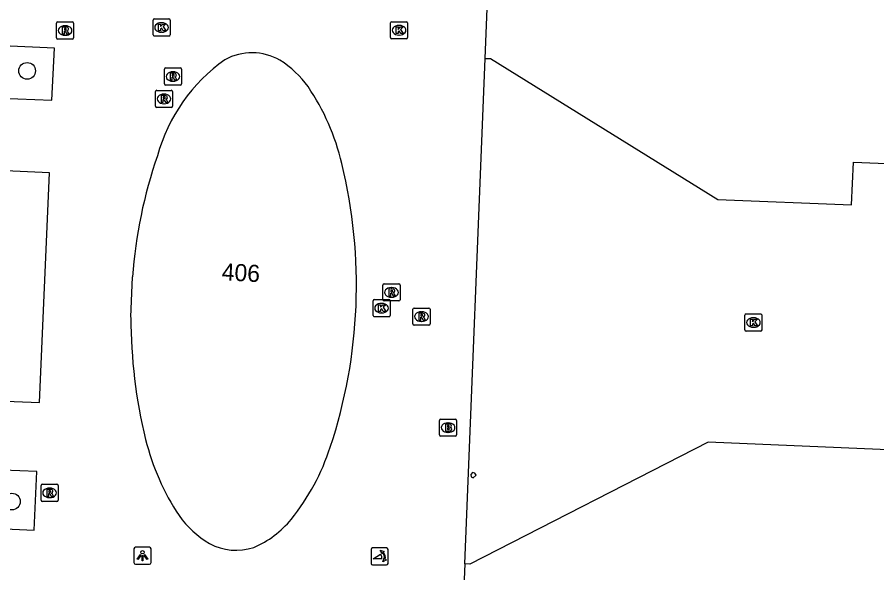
# Model space of a CAD drawing. Extents: x 160891 to 161384, y 386490 to 386907.
# Drawn here: x 161040.5 to 161090.7, y 386704.8 to 386737.3 of the extents above; entities that cross this region are included whole.
import ezdxf

# ---------------------------------------------------------------- set-up
doc = ezdxf.new("R2010")
doc.units = 0
for name, color, linetype in [('IMGEO_Boom', 7, 'Continuous'), ('IMGEO_Brandkraan', 7, 'Continuous'), ('IMGEO_Kolk', 7, 'Continuous'), ('IMGEO_Lichtpunt', 7, 'Continuous'), ('IMGEO_Pand', 7, 'Continuous'), ('IMGEO_Pand_nummerreeks', 7, 'Continuous'), ('IMGEO_Poller', 7, 'Continuous'), ('IMGEO_Rioolput', 7, 'Continuous'), ('IMGEO_Voetpad_open', 7, 'Continuous')]:
    doc.layers.add(name, color=color, linetype=linetype)

msp = doc.modelspace()

# ---------------------------------------------------------------- linework, layer by layer
at = {"layer": 'IMGEO_Boom'}
for centre in [(161041.064, 386734.18), (161040.172, 386709.011)]:
    msp.add_circle(centre, 0.489, dxfattribs=at)
at = {"layer": 'IMGEO_Brandkraan'}
for p, q in [((161065.15, 386712.904), (161065.15, 386713.756)), ((161065.225, 386713.83), (161066.077, 386713.83)), ((161066.151, 386713.756), (161066.151, 386712.904)), ((161065.638, 386713.61), (161065.663, 386713.61)), ((161066.077, 386712.83), (161065.225, 386712.83)), ((161065.661, 386713.05), (161065.636, 386713.05))]:
    msp.add_line(p, q, dxfattribs=at)
for points in [[(161065.15, 386712.904), (161065.15, 386713.756)], [(161065.225, 386713.83), (161066.077, 386713.83)], [(161066.151, 386713.756), (161066.151, 386712.904)], [(161065.498, 386713.53), (161065.498, 386713.13), (161065.711, 386713.13)], [(161065.729, 386713.53), (161065.498, 386713.53)], [(161065.677, 386713.449), (161065.623, 386713.449), (161065.623, 386713.373)], [(161065.623, 386713.373), (161065.676, 386713.373)], [(161065.685, 386713.297), (161065.623, 386713.297), (161065.623, 386713.216)], [(161065.623, 386713.216), (161065.685, 386713.216)], [(161066.077, 386712.83), (161065.225, 386712.83)]]:
    msp.add_lwpolyline(points, dxfattribs=at)
for centre, radius, start, end in [((161065.227, 386713.754), 0.0765, 91.552, 178.448), ((161065.227, 386713.754), 0.0765, 91.552, 178.448), ((161066.075, 386713.754), 0.0765, 1.552, 88.448), ((161066.075, 386713.754), 0.0765, 1.552, 88.448), ((161065.678, 386713.411), 0.0379, 267.8285, 90.9355), ((161065.686, 386713.256), 0.0404, 269.8759, 90.5077), ((161065.733, 386713.385), 0.145, 59.4692, 91.5367), ((161065.758, 386713.432), 0.0922, 285.5137, 58.1501), ((161065.763, 386713.24), 0.105, 301.3115, 78.989), ((161065.227, 386712.906), 0.0765, 181.552, 268.448), ((161065.227, 386712.906), 0.0765, 181.552, 268.448), ((161065.717, 386713.381), 0.251, 268.6676, 293.5347), ((161066.075, 386712.906), 0.0765, 271.552, 358.448), ((161066.075, 386712.906), 0.0765, 271.552, 358.448)]:
    msp.add_arc(centre, radius, start, end, dxfattribs=at)
for centre, major_axis, ratio, start_param, end_param in [((161065.637, 386713.33), (-0.387, 0.002), 0.722429, 4.712389, 7.853982), ((161065.662, 386713.33), (-0.39, 0.002), 0.717154, 1.570796, 4.712389)]:
    msp.add_ellipse(centre, major_axis=major_axis, ratio=ratio, start_param=start_param, end_param=end_param, dxfattribs=at)
at = {"layer": 'IMGEO_Kolk'}
for p, q in [((161048.417, 386736.292), (161048.417, 386737.144)), ((161048.492, 386737.218), (161049.344, 386737.218)), ((161048.905, 386736.998), (161048.93, 386736.998)), ((161049.418, 386737.144), (161049.418, 386736.292)), ((161062.29, 386736.131), (161062.29, 386736.983)), ((161062.365, 386737.057), (161063.217, 386737.057)), ((161062.778, 386736.837), (161062.803, 386736.837)), ((161063.291, 386736.983), (161063.291, 386736.131)), ((161048.928, 386736.438), (161048.903, 386736.438)), ((161049.344, 386736.218), (161048.492, 386736.218)), ((161063.217, 386736.057), (161062.365, 386736.057)), ((161062.801, 386736.277), (161062.776, 386736.277)), ((161061.269, 386719.888), (161061.269, 386720.74)), ((161061.344, 386720.814), (161062.196, 386720.814)), ((161062.27, 386720.74), (161062.27, 386719.888)), ((161061.757, 386720.594), (161061.782, 386720.594)), ((161062.196, 386719.814), (161061.344, 386719.814)), ((161061.78, 386720.034), (161061.755, 386720.034)), ((161082.987, 386719.047), (161082.987, 386719.899)), ((161083.062, 386719.973), (161083.914, 386719.973)), ((161083.475, 386719.753), (161083.5, 386719.753)), ((161083.988, 386719.899), (161083.988, 386719.047)), ((161083.914, 386718.973), (161083.062, 386718.973)), ((161083.498, 386719.193), (161083.473, 386719.193))]:
    msp.add_line(p, q, dxfattribs=at)
for points in [[(161048.417, 386736.292), (161048.417, 386737.144)], [(161048.492, 386737.218), (161049.344, 386737.218)], [(161048.738, 386736.918), (161048.861, 386736.918), (161048.861, 386736.767), (161048.991, 386736.918), (161049.155, 386736.918), (161049.009, 386736.767), (161049.162, 386736.518), (161049.01, 386736.518), (161048.925, 386736.682), (161048.861, 386736.615), (161048.861, 386736.518), (161048.738, 386736.518), (161048.738, 386736.918)], [(161049.418, 386737.144), (161049.418, 386736.292)], [(161062.29, 386736.131), (161062.29, 386736.983)], [(161062.365, 386737.057), (161063.217, 386737.057)], [(161063.291, 386736.983), (161063.291, 386736.131)], [(161062.611, 386736.757), (161062.734, 386736.757), (161062.734, 386736.606), (161062.864, 386736.757), (161063.028, 386736.757), (161062.882, 386736.606), (161063.035, 386736.357), (161062.883, 386736.357), (161062.798, 386736.521), (161062.734, 386736.454), (161062.734, 386736.357), (161062.611, 386736.357), (161062.611, 386736.757)], [(161049.344, 386736.218), (161048.492, 386736.218)], [(161063.217, 386736.057), (161062.365, 386736.057)], [(161061.269, 386719.888), (161061.269, 386720.74)], [(161061.344, 386720.814), (161062.196, 386720.814)], [(161062.27, 386720.74), (161062.27, 386719.888)], [(161061.59, 386720.514), (161061.713, 386720.514), (161061.713, 386720.363), (161061.843, 386720.514), (161062.007, 386720.514), (161061.861, 386720.363), (161062.014, 386720.114), (161061.862, 386720.114), (161061.777, 386720.278), (161061.713, 386720.211), (161061.713, 386720.114), (161061.59, 386720.114), (161061.59, 386720.514)], [(161062.196, 386719.814), (161061.344, 386719.814)], [(161082.987, 386719.047), (161082.987, 386719.899)], [(161083.062, 386719.973), (161083.914, 386719.973)], [(161083.988, 386719.899), (161083.988, 386719.047)], [(161083.308, 386719.673), (161083.431, 386719.673), (161083.431, 386719.522), (161083.561, 386719.673), (161083.725, 386719.673), (161083.579, 386719.522), (161083.732, 386719.273), (161083.58, 386719.273), (161083.495, 386719.437), (161083.431, 386719.37), (161083.431, 386719.273), (161083.308, 386719.273), (161083.308, 386719.673)], [(161083.914, 386718.973), (161083.062, 386718.973)]]:
    msp.add_lwpolyline(points, dxfattribs=at)
for centre, start, end in [((161048.494, 386737.142), 91.552, 178.448), ((161048.494, 386737.142), 91.552, 178.448), ((161049.342, 386737.142), 1.552, 88.448), ((161049.342, 386737.142), 1.552, 88.448), ((161062.367, 386736.981), 91.552, 178.448), ((161062.367, 386736.981), 91.552, 178.448), ((161063.215, 386736.981), 1.552, 88.448), ((161063.215, 386736.981), 1.552, 88.448), ((161048.494, 386736.294), 181.552, 268.448), ((161048.494, 386736.294), 181.552, 268.448), ((161049.342, 386736.294), 271.552, 358.448), ((161049.342, 386736.294), 271.552, 358.448), ((161062.367, 386736.133), 181.552, 268.448), ((161062.367, 386736.133), 181.552, 268.448), ((161063.215, 386736.133), 271.552, 358.448), ((161063.215, 386736.133), 271.552, 358.448), ((161061.346, 386720.738), 91.552, 178.448), ((161061.346, 386720.738), 91.552, 178.448), ((161062.194, 386720.738), 1.552, 88.448), ((161062.194, 386720.738), 1.552, 88.448), ((161061.346, 386719.89), 181.552, 268.448), ((161061.346, 386719.89), 181.552, 268.448), ((161062.194, 386719.89), 271.552, 358.448), ((161062.194, 386719.89), 271.552, 358.448), ((161083.064, 386719.897), 91.552, 178.448), ((161083.064, 386719.897), 91.552, 178.448), ((161083.912, 386719.897), 1.552, 88.448), ((161083.912, 386719.897), 1.552, 88.448), ((161083.064, 386719.049), 181.552, 268.448), ((161083.064, 386719.049), 181.552, 268.448), ((161083.912, 386719.049), 271.552, 358.448), ((161083.912, 386719.049), 271.552, 358.448)]:
    msp.add_arc(centre, 0.0765, start, end, dxfattribs=at)
for centre, major_axis, ratio, start_param, end_param in [((161048.904, 386736.718), (-0.387, 0.002), 0.722429, 4.712389, 7.853982), ((161048.929, 386736.718), (-0.39, 0.002), 0.717154, 1.570796, 4.712389), ((161062.777, 386736.557), (-0.387, 0.002), 0.722429, 4.712389, 7.853982), ((161062.802, 386736.557), (-0.39, 0.002), 0.717154, 1.570796, 4.712389), ((161061.756, 386720.314), (-0.387, 0.002), 0.722429, 4.712389, 7.853982), ((161061.781, 386720.314), (-0.39, 0.002), 0.717154, 1.570796, 4.712389), ((161083.474, 386719.473), (-0.387, 0.002), 0.722429, 4.712389, 7.853982), ((161083.499, 386719.473), (-0.39, 0.002), 0.717154, 1.570796, 4.712389)]:
    msp.add_ellipse(centre, major_axis=major_axis, ratio=ratio, start_param=start_param, end_param=end_param, dxfattribs=at)
at = {"layer": 'IMGEO_Lichtpunt'}
for p, q in [((161047.304, 386706.247), (161047.304, 386705.44)), ((161047.304, 386706.247), (161047.304, 386705.44)), ((161048.206, 386706.342), (161047.398, 386706.342)), ((161048.206, 386706.342), (161047.398, 386706.342)), ((161048.3, 386705.44), (161048.3, 386706.247)), ((161048.3, 386705.44), (161048.3, 386706.247)), ((161047.398, 386705.346), (161048.206, 386705.346)), ((161047.398, 386705.346), (161048.206, 386705.346))]:
    msp.add_line(p, q, dxfattribs=at)
for points in [[(161047.678, 386705.911), (161047.717, 386705.883), (161047.529, 386705.621), (161047.491, 386705.648), (161047.678, 386705.911)], [(161047.78, 386705.863), (161047.827, 386705.863), (161047.827, 386705.541), (161047.78, 386705.541), (161047.78, 386705.863)], [(161047.89, 386705.883), (161047.928, 386705.91), (161048.115, 386705.648), (161048.076, 386705.62), (161047.89, 386705.883)]]:
    msp.add_lwpolyline(points, dxfattribs=at)
msp.add_circle((161047.803, 386706.045), 0.0994, dxfattribs=at)
for centre, start, end in [((161047.398, 386706.247), 90, 180), ((161047.398, 386706.247), 90, 180), ((161048.206, 386706.247), 0, 90), ((161048.206, 386706.247), 0, 90), ((161047.398, 386705.44), 180, 270), ((161047.398, 386705.44), 180, 270), ((161048.206, 386705.44), 270, 0), ((161048.206, 386705.44), 270, 360)]:
    msp.add_arc(centre, 0.0946, start, end, dxfattribs=at)
at = {"layer": 'IMGEO_Pand'}
for points in [[(161067.82, 386734.914), (161068.422, 386750), (161068.579, 386753.93)], [(161067.82, 386734.914), (161068.128, 386734.901), (161081.411, 386726.666), (161089.223, 386726.344), (161089.335, 386728.855), (161138.981, 386726.813), (161138.885, 386724.445), (161161.551, 386723.521)], [(161047.127, 386719.777), (161047.22, 386722.145)], [(161127.462, 386710.495), (161080.851, 386712.475), (161066.929, 386705.356), (161066.624, 386705.366)], [(161067.221, 386710.676), (161067.078, 386710.699), (161066.975, 386710.596), (161066.998, 386710.453), (161067.127, 386710.387), (161067.287, 386710.547), (161067.221, 386710.676)], [(161066.624, 386705.366), (161065.189, 386671.013)]]:
    msp.add_lwpolyline(points, dxfattribs=at)
for centre, radius, start, end in [((161058.492, 386726.517), 10.182, 125.2343, 164.6202), ((161054.196, 386731.963), 3.275, 59.9847, 118.8039), ((161052.785, 386729.913), 5.759, 35.5324, 58.0373), ((161046.426, 386725.74), 13.363, 13.0848, 34.2475), ((161074.964, 386720.123), 27.818, 160.9175, 175.8307), ((161030.326, 386721.647), 29.974, 341.6232, 13.7384), ((161077.018, 386719.752), 29.891, 179.953, 193.7693), ((161061.976, 386716.123), 14.418, 193.9898, 213.4039), ((161045.912, 386716.393), 13.527, 321.4821, 341.9293), ((161054.654, 386711.527), 5.778, 215.3302, 239.4389), ((161051.945, 386711.745), 5.912, 293.5352, 320.3134), ((161053.283, 386709.533), 3.368, 242.2634, 287.6749)]:
    msp.add_arc(centre, radius, start, end, dxfattribs=at)
at = {"layer": 'IMGEO_Poller'}
for p, q in [((161061.151, 386706.205), (161061.151, 386705.398)), ((161061.151, 386706.205), (161061.151, 386705.398)), ((161062.053, 386706.3), (161061.245, 386706.3)), ((161062.053, 386706.3), (161061.245, 386706.3)), ((161062.147, 386705.398), (161062.147, 386706.205)), ((161062.147, 386705.398), (161062.147, 386706.205)), ((161061.245, 386705.303), (161062.053, 386705.303)), ((161061.245, 386705.303), (161062.053, 386705.303))]:
    msp.add_line(p, q, dxfattribs=at)
for points in [[(161061.786, 386705.656), (161061.273, 386705.656), (161061.703, 386705.931)], [(161061.83, 386706.029), (161061.818, 386705.956), (161061.693, 386706.161)], [(161061.693, 386706.161), (161061.924, 386706.095), (161061.853, 386706.063)], [(161061.846, 386705.484), (161061.912, 386705.715), (161061.942, 386705.647)], [(161061.978, 386705.62), (161062.05, 386705.609), (161061.846, 386705.484)]]:
    msp.add_lwpolyline(points, dxfattribs=at)
for centre, radius, start, end in [((161061.245, 386706.205), 0.0946, 90, 180), ((161061.245, 386706.205), 0.0946, 90, 180), ((161062.053, 386706.205), 0.0946, 0, 90), ((161062.053, 386706.205), 0.0946, 0, 90), ((161061.458, 386705.706), 0.332, 351.3247, 42.4854), ((161061.472, 386705.716), 0.476, 351.7527, 41.1691), ((161061.472, 386705.716), 0.516, 349.3569, 42.2912), ((161061.245, 386705.398), 0.0946, 180, 270), ((161061.245, 386705.398), 0.0946, 180, 270), ((161062.053, 386705.398), 0.0946, 270, 0), ((161062.053, 386705.398), 0.0946, 270, 0)]:
    msp.add_arc(centre, radius, start, end, dxfattribs=at)
at = {"layer": 'IMGEO_Rioolput'}
for p, q in [((161042.781, 386736.115), (161042.781, 386736.967)), ((161042.856, 386737.041), (161043.708, 386737.041)), ((161043.269, 386736.821), (161043.294, 386736.821)), ((161043.782, 386736.967), (161043.782, 386736.115)), ((161043.708, 386736.041), (161042.856, 386736.041)), ((161043.292, 386736.261), (161043.267, 386736.261)), ((161049.158, 386734.353), (161050.01, 386734.353)), ((161049.083, 386733.427), (161049.083, 386734.279)), ((161049.571, 386734.133), (161049.596, 386734.133)), ((161050.084, 386734.279), (161050.084, 386733.427)), ((161050.01, 386733.353), (161049.158, 386733.353)), ((161049.594, 386733.573), (161049.569, 386733.573)), ((161048.559, 386732.118), (161048.559, 386732.97)), ((161048.634, 386733.044), (161049.486, 386733.044)), ((161049.047, 386732.824), (161049.072, 386732.824)), ((161049.56, 386732.97), (161049.56, 386732.118)), ((161049.486, 386732.044), (161048.634, 386732.044)), ((161049.07, 386732.264), (161049.045, 386732.264)), ((161061.921, 386721.733), (161062.773, 386721.733)), ((161061.846, 386720.807), (161061.846, 386721.659)), ((161062.334, 386721.513), (161062.359, 386721.513)), ((161062.847, 386721.659), (161062.847, 386720.807)), ((161062.773, 386720.733), (161061.921, 386720.733)), ((161062.357, 386720.953), (161062.332, 386720.953)), ((161063.598, 386719.394), (161063.598, 386720.246)), ((161063.673, 386720.32), (161064.525, 386720.32)), ((161064.599, 386720.246), (161064.599, 386719.394)), ((161064.086, 386720.1), (161064.111, 386720.1)), ((161064.525, 386719.32), (161063.673, 386719.32)), ((161064.109, 386719.54), (161064.084, 386719.54)), ((161041.877, 386709.093), (161041.877, 386709.945)), ((161041.952, 386710.019), (161042.804, 386710.019)), ((161042.365, 386709.799), (161042.39, 386709.799)), ((161042.878, 386709.945), (161042.878, 386709.093)), ((161042.388, 386709.239), (161042.363, 386709.239)), ((161042.804, 386709.019), (161041.952, 386709.019))]:
    msp.add_line(p, q, dxfattribs=at)
for points in [[(161042.781, 386736.115), (161042.781, 386736.967)], [(161042.856, 386737.041), (161043.708, 386737.041)], [(161043.782, 386736.967), (161043.782, 386736.115)], [(161043.37, 386736.739), (161043.118, 386736.741), (161043.118, 386736.341)], [(161043.118, 386736.341), (161043.242, 386736.341), (161043.242, 386736.503), (161043.253, 386736.503)], [(161043.296, 386736.66), (161043.242, 386736.66), (161043.242, 386736.579)], [(161043.242, 386736.579), (161043.294, 386736.579)], [(161043.3, 386736.474), (161043.371, 386736.341), (161043.511, 386736.341), (161043.446, 386736.467)], [(161043.708, 386736.041), (161042.856, 386736.041)], [(161049.158, 386734.353), (161050.01, 386734.353)], [(161049.083, 386733.427), (161049.083, 386734.279)], [(161049.672, 386734.051), (161049.42, 386734.053), (161049.42, 386733.653)], [(161049.42, 386733.653), (161049.544, 386733.653), (161049.544, 386733.815), (161049.555, 386733.815)], [(161049.598, 386733.972), (161049.544, 386733.972), (161049.544, 386733.891)], [(161049.544, 386733.891), (161049.596, 386733.891)], [(161049.602, 386733.786), (161049.673, 386733.653), (161049.813, 386733.653), (161049.748, 386733.779)], [(161050.084, 386734.279), (161050.084, 386733.427)], [(161050.01, 386733.353), (161049.158, 386733.353)], [(161048.559, 386732.118), (161048.559, 386732.97)], [(161048.634, 386733.044), (161049.486, 386733.044)], [(161049.56, 386732.97), (161049.56, 386732.118)], [(161049.148, 386732.742), (161048.896, 386732.744), (161048.896, 386732.344)], [(161048.896, 386732.344), (161049.02, 386732.344), (161049.02, 386732.506), (161049.031, 386732.506)], [(161049.074, 386732.663), (161049.02, 386732.663), (161049.02, 386732.582)], [(161049.02, 386732.582), (161049.072, 386732.582)], [(161049.078, 386732.477), (161049.149, 386732.344), (161049.289, 386732.344), (161049.224, 386732.47)], [(161049.486, 386732.044), (161048.634, 386732.044)], [(161061.921, 386721.733), (161062.773, 386721.733)], [(161061.846, 386720.807), (161061.846, 386721.659)], [(161062.435, 386721.431), (161062.183, 386721.433), (161062.183, 386721.033)], [(161062.361, 386721.352), (161062.307, 386721.352), (161062.307, 386721.271)], [(161062.307, 386721.271), (161062.359, 386721.271)], [(161062.847, 386721.659), (161062.847, 386720.807)], [(161062.773, 386720.733), (161061.921, 386720.733)], [(161062.183, 386721.033), (161062.307, 386721.033), (161062.307, 386721.195), (161062.318, 386721.195)], [(161062.365, 386721.166), (161062.436, 386721.033), (161062.576, 386721.033), (161062.511, 386721.159)], [(161063.598, 386719.394), (161063.598, 386720.246)], [(161063.673, 386720.32), (161064.525, 386720.32)], [(161064.599, 386720.246), (161064.599, 386719.394)], [(161064.187, 386720.018), (161063.935, 386720.02), (161063.935, 386719.62)], [(161063.935, 386719.62), (161064.059, 386719.62), (161064.059, 386719.782), (161064.07, 386719.782)], [(161064.113, 386719.939), (161064.059, 386719.939), (161064.059, 386719.858)], [(161064.059, 386719.858), (161064.111, 386719.858)], [(161064.117, 386719.753), (161064.188, 386719.62), (161064.328, 386719.62), (161064.263, 386719.746)], [(161064.525, 386719.32), (161063.673, 386719.32)], [(161041.877, 386709.093), (161041.877, 386709.945)], [(161041.952, 386710.019), (161042.804, 386710.019)], [(161042.466, 386709.717), (161042.214, 386709.719), (161042.214, 386709.319)], [(161042.878, 386709.945), (161042.878, 386709.093)], [(161042.214, 386709.319), (161042.338, 386709.319), (161042.338, 386709.481), (161042.349, 386709.481)], [(161042.392, 386709.638), (161042.338, 386709.638), (161042.338, 386709.557)], [(161042.338, 386709.557), (161042.39, 386709.557)], [(161042.396, 386709.452), (161042.467, 386709.319), (161042.607, 386709.319), (161042.542, 386709.445)], [(161042.804, 386709.019), (161041.952, 386709.019)]]:
    msp.add_lwpolyline(points, dxfattribs=at)
for centre, radius, start, end in [((161042.858, 386736.965), 0.0765, 91.552, 178.448), ((161042.858, 386736.965), 0.0765, 91.552, 178.448), ((161043.706, 386736.965), 0.0765, 1.552, 88.448), ((161043.706, 386736.965), 0.0765, 1.552, 88.448), ((161043.252, 386736.45), 0.0533, 26.0293, 88.6989), ((161043.278, 386736.768), 0.19, 274.7715, 282.9687), ((161043.302, 386736.564), 0.0964, 77.0061, 93.1865), ((161043.316, 386736.621), 0.0378, 276.6634, 79.6772), ((161043.369, 386736.629), 0.109, 350.3612, 89.416), ((161043.367, 386736.629), 0.112, 277.5842, 350.9817), ((161043.351, 386736.414), 0.108, 29.5134, 73.7905), ((161042.858, 386736.117), 0.0765, 181.552, 268.448), ((161042.858, 386736.117), 0.0765, 181.552, 268.448), ((161043.706, 386736.117), 0.0765, 271.552, 358.448), ((161043.706, 386736.117), 0.0765, 271.552, 358.448), ((161049.16, 386734.277), 0.0765, 91.552, 178.448), ((161049.16, 386734.277), 0.0765, 91.552, 178.448), ((161050.008, 386734.277), 0.0765, 1.552, 88.448), ((161050.008, 386734.277), 0.0765, 1.552, 88.448), ((161049.554, 386733.762), 0.0533, 26.0293, 88.6989), ((161049.58, 386734.08), 0.19, 274.7715, 282.9687), ((161049.604, 386733.876), 0.0964, 77.0061, 93.1865), ((161049.618, 386733.933), 0.0378, 276.6634, 79.6772), ((161049.671, 386733.941), 0.109, 350.3612, 89.416), ((161049.669, 386733.941), 0.112, 277.5842, 350.9817), ((161049.653, 386733.726), 0.108, 29.5134, 73.7905), ((161049.16, 386733.429), 0.0765, 181.552, 268.448), ((161049.16, 386733.429), 0.0765, 181.552, 268.448), ((161050.008, 386733.429), 0.0765, 271.552, 358.448), ((161050.008, 386733.429), 0.0765, 271.552, 358.448), ((161048.636, 386732.968), 0.0765, 91.552, 178.448), ((161048.636, 386732.968), 0.0765, 91.552, 178.448), ((161049.484, 386732.968), 0.0765, 1.552, 88.448), ((161049.484, 386732.968), 0.0765, 1.552, 88.448), ((161049.03, 386732.453), 0.0533, 26.0293, 88.6989), ((161049.056, 386732.771), 0.19, 274.7715, 282.9687), ((161049.08, 386732.567), 0.0964, 77.0061, 93.1865), ((161049.094, 386732.624), 0.0378, 276.6634, 79.6772), ((161049.147, 386732.632), 0.109, 350.3612, 89.416), ((161049.145, 386732.632), 0.112, 277.5842, 350.9817), ((161049.129, 386732.417), 0.108, 29.5134, 73.7905), ((161048.636, 386732.12), 0.0765, 181.552, 268.448), ((161048.636, 386732.12), 0.0765, 181.552, 268.448), ((161049.484, 386732.12), 0.0765, 271.552, 358.448), ((161049.484, 386732.12), 0.0765, 271.552, 358.448), ((161061.923, 386721.657), 0.0765, 91.552, 178.448), ((161061.923, 386721.657), 0.0765, 91.552, 178.448), ((161062.771, 386721.657), 0.0765, 1.552, 88.448), ((161062.771, 386721.657), 0.0765, 1.552, 88.448), ((161062.343, 386721.46), 0.19, 274.7715, 282.9687), ((161062.367, 386721.256), 0.0964, 77.0061, 93.1865), ((161062.381, 386721.313), 0.0378, 276.6634, 79.6772), ((161062.434, 386721.321), 0.109, 350.3612, 89.416), ((161062.432, 386721.321), 0.112, 277.5842, 350.9817), ((161061.923, 386720.809), 0.0765, 181.552, 268.448), ((161061.923, 386720.809), 0.0765, 181.552, 268.448), ((161062.317, 386721.142), 0.0533, 26.0293, 88.6989), ((161062.416, 386721.106), 0.108, 29.5134, 73.7905), ((161062.771, 386720.809), 0.0765, 271.552, 358.448), ((161062.771, 386720.809), 0.0765, 271.552, 358.448), ((161063.675, 386720.244), 0.0765, 91.552, 178.448), ((161063.675, 386720.244), 0.0765, 91.552, 178.448), ((161064.523, 386720.244), 0.0765, 1.552, 88.448), ((161064.523, 386720.244), 0.0765, 1.552, 88.448), ((161064.069, 386719.729), 0.0533, 26.0293, 88.6989), ((161064.095, 386720.047), 0.19, 274.7715, 282.9687), ((161064.119, 386719.843), 0.0964, 77.0061, 93.1865), ((161064.133, 386719.9), 0.0378, 276.6634, 79.6772), ((161064.186, 386719.908), 0.109, 350.3612, 89.416), ((161064.184, 386719.908), 0.112, 277.5842, 350.9817), ((161064.168, 386719.693), 0.108, 29.5134, 73.7905), ((161063.675, 386719.396), 0.0765, 181.552, 268.448), ((161063.675, 386719.396), 0.0765, 181.552, 268.448), ((161064.523, 386719.396), 0.0765, 271.552, 358.448), ((161064.523, 386719.396), 0.0765, 271.552, 358.448), ((161041.954, 386709.943), 0.0765, 91.552, 178.448), ((161041.954, 386709.943), 0.0765, 91.552, 178.448), ((161042.465, 386709.607), 0.109, 350.3612, 89.416), ((161042.802, 386709.943), 0.0765, 1.552, 88.448), ((161042.802, 386709.943), 0.0765, 1.552, 88.448), ((161042.348, 386709.428), 0.0533, 26.0293, 88.6989), ((161042.374, 386709.746), 0.19, 274.7715, 282.9687), ((161042.398, 386709.542), 0.0964, 77.0061, 93.1865), ((161042.412, 386709.599), 0.0378, 276.6634, 79.6772), ((161042.463, 386709.607), 0.112, 277.5842, 350.9817), ((161042.447, 386709.392), 0.108, 29.5134, 73.7905), ((161041.954, 386709.095), 0.0765, 181.552, 268.448), ((161041.954, 386709.095), 0.0765, 181.552, 268.448), ((161042.802, 386709.095), 0.0765, 271.552, 358.448), ((161042.802, 386709.095), 0.0765, 271.552, 358.448)]:
    msp.add_arc(centre, radius, start, end, dxfattribs=at)
for centre, major_axis, ratio, start_param, end_param in [((161043.268, 386736.541), (-0.387, 0.002), 0.722429, 4.712389, 7.853982), ((161043.293, 386736.541), (-0.39, 0.002), 0.717154, 1.570796, 4.712389), ((161049.57, 386733.853), (-0.387, 0.002), 0.722429, 4.712389, 7.853982), ((161049.595, 386733.853), (-0.39, 0.002), 0.717154, 1.570796, 4.712389), ((161049.046, 386732.544), (-0.387, 0.002), 0.722429, 4.712389, 7.853982), ((161049.071, 386732.544), (-0.39, 0.002), 0.717154, 1.570796, 4.712389), ((161062.333, 386721.233), (-0.387, 0.002), 0.722429, 4.712389, 7.853982), ((161062.358, 386721.233), (-0.39, 0.002), 0.717154, 1.570796, 4.712389), ((161064.085, 386719.82), (-0.387, 0.002), 0.722429, 4.712389, 7.853982), ((161064.11, 386719.82), (-0.39, 0.002), 0.717154, 1.570796, 4.712389), ((161042.364, 386709.519), (-0.387, 0.002), 0.722429, 4.712389, 7.853982), ((161042.389, 386709.519), (-0.39, 0.002), 0.717154, 1.570796, 4.712389)]:
    msp.add_ellipse(centre, major_axis=major_axis, ratio=ratio, start_param=start_param, end_param=end_param, dxfattribs=at)
at = {"layer": 'IMGEO_Voetpad_open'}
for points in [[(161039.526, 386732.596), (161042.513, 386732.464), (161042.656, 386735.511), (161039.638, 386735.641), (161039.526, 386732.596)], [(161066.624, 386705.366), (161067.82, 386734.914)], [(161038.802, 386714.912), (161041.789, 386714.797), (161042.363, 386728.229), (161039.349, 386728.359), (161038.802, 386714.912)], [(161038.486, 386707.47), (161041.484, 386707.334), (161041.637, 386710.771), (161038.63, 386710.889), (161038.486, 386707.47)]]:
    msp.add_lwpolyline(points, dxfattribs=at)

# ---------------------------------------------------------------- texts
at = {"layer": 'IMGEO_Pand_nummerreeks'}
msp.add_text('406', height=1, rotation=356.8911, dxfattribs=at).set_placement((161052.412, 386721.951))

doc.saveas('drawing.dxf')
